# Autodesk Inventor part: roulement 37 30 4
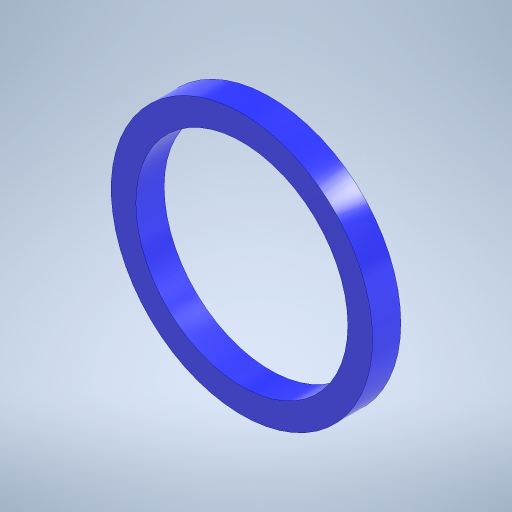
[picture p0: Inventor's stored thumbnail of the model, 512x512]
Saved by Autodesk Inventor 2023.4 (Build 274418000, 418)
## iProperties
Created: 2025-06
Part Number: roulement 37 30 4
Material: Acier
Document SubType Name: Modeling
Designer: mel
Density: 7.85 g/cm^3
Appearance: Bleu - Peinture murale - Brillant
Author: mel
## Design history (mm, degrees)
sketch "Esquisse1"
  geometry: C1 r 15 at (0, 0); C2 r 18.5 at (0, 0); 1 further point
  constraints: 2 centre point, 2 coincident
  dimensions: "d0" = 30 diameter of C1; "d1" = 37 diameter of C2
extrude "Extrusion1" new body sketch "Esquisse1" distance "d2" = 4; taper "d3" = 0 deg
node "Solide1"
